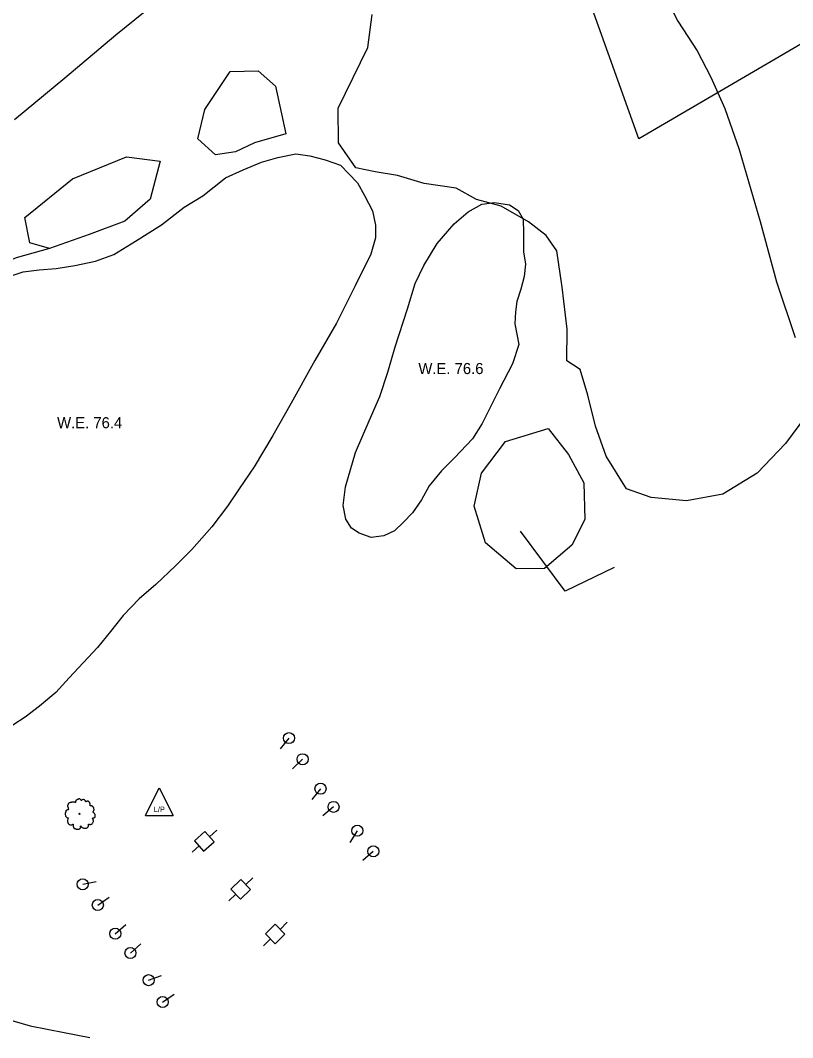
# Model space of a CAD drawing. Extents: x 2161152 to 2175754, y 602179 to 617749.
# Drawn here: x 2172503.3 to 2172781.8, y 613495.8 to 613862.8 of the extents above; entities that cross this region are included whole.
import ezdxf

# ---------------------------------------------------------------- set-up
doc = ezdxf.new("R2010")
doc.units = 0
for name, color, linetype in [('RD_EX_Driveway_Dirt', 7, 'Continuous'), ('RD_EX_Fence_ChLk', 7, 'Continuous'), ('RD_EX_H2O', 7, 'Continuous'), ('RD_EX_H2O_txCode', 7, 'Continuous'), ('RD_EX_UT', 7, 'Continuous'), ('RD_EX_VEG', 7, 'Continuous')]:
    doc.layers.add(name, color=color, linetype=linetype)

msp = doc.modelspace()

# ---------------------------------------------------------------- linework, layer by layer
at = {"layer": 'RD_EX_Driveway_Dirt'}
msp.add_lwpolyline([(2172493.13, 613504.13), (2172506.78, 613500.11), (2172519.03, 613497.66), (2172528.38, 613495.84)], dxfattribs=at)
at = {"layer": 'RD_EX_Fence_ChLk'}
for points in [[(2172849.56, 613892.25), (2172726.3, 613820.12), (2172700.67, 613891.74), (2172702.95, 613909.79), (2172721.51, 613939.42), (2172751.74, 613974.63), (2172793.62, 613997.53), (2172878.3, 614033.31), (2172955.81, 614058.36), (2172981.68, 614063.33), (2173110.09, 614093.24)], [(2172717.4, 613665.4), (2172699.75, 613656.86), (2172683.65, 613678.5)]]:
    msp.add_lwpolyline(points, dxfattribs=at)
at = {"layer": 'RD_EX_H2O'}
for points in [[(2172497.49, 613769.8), (2172504.35, 613772.09), (2172510.1, 613772.82), (2172516.17, 613773.34), (2172522.92, 613774.37), (2172530.42, 613775.98), (2172536.95, 613778.35), (2172544.76, 613783.2), (2172554.14, 613789.12), (2172562.4, 613795.42), (2172569.12, 613799.51), (2172577.26, 613806.08), (2172583.67, 613808.85), (2172590.21, 613811.62), (2172596.19, 613813.34), (2172602.68, 613814.65), (2172607.71, 613813.94), (2172613.17, 613812.49), (2172618.76, 613810.64), (2172621.71, 613807.48), (2172624.86, 613804.25), (2172627.36, 613799.64), (2172630.22, 613794.09), (2172631.31, 613788.93), (2172631.35, 613784.35), (2172629.62, 613778.49), (2172623.98, 613767.05), (2172617.26, 613753.58), (2172609.49, 613740.15), (2172600.98, 613724.75), (2172594.33, 613713.01), (2172587.62, 613701.74), (2172582.16, 613693.81), (2172577.96, 613687.57), (2172572.39, 613680.18), (2172565.12, 613671.98), (2172559.26, 613666), (2172552.12, 613659.33), (2172546.15, 613654.15), (2172540.36, 613648.09), (2172535.77, 613642.4), (2172531.05, 613636.57), (2172520.9, 613625.68), (2172516.13, 613620.33), (2172510.17, 613615.41), (2172504.98, 613611.46), (2172500.62, 613608.55)], [(2172634.32, 613676.84), (2172629.78, 613676.33), (2172625.44, 613677.81), (2172622.71, 613679.63), (2172620.7, 613682.89), (2172619.67, 613687.85), (2172620.5, 613694.54), (2172624.18, 613706.98), (2172629.1, 613718.38), (2172632.86, 613727.16), (2172635.82, 613735.97), (2172638.39, 613745.06), (2172642.92, 613758.8), (2172645.62, 613767.88), (2172648.77, 613774.42), (2172653.63, 613782.29), (2172659.72, 613789.4), (2172664.73, 613793.81), (2172669.74, 613796.56), (2172674.22, 613797.14), (2172679.64, 613796.29), (2172682.76, 613794.19), (2172684.58, 613791.14), (2172684.74, 613786.01), (2172684.7, 613779.3), (2172685.41, 613774.82), (2172685, 613770.45), (2172683.71, 613765.9), (2172682.36, 613761.43), (2172681.84, 613757.72), (2172681.62, 613753.41), (2172683.02, 613745.85), (2172680.79, 613738.88), (2172676.09, 613729.86), (2172669.81, 613717.45), (2172666.3, 613711.85), (2172659.88, 613704.96), (2172655.2, 613700.33), (2172650.69, 613694.96), (2172647.92, 613689.81), (2172644.64, 613685.2), (2172641.33, 613681.72), (2172638.23, 613678.7), (2172634.32, 613676.84)]]:
    msp.add_lwpolyline(points, dxfattribs=at)
at = {"layer": 'RD_EX_UT'}
for p, q in [((2172600.14, 613603.9), (2172596.94, 613600.06)), ((2172605.06, 613596.28), (2172601.41, 613592.87)), ((2172548.39, 613575.93), (2172553.39, 613585.93)), ((2172553.39, 613585.93), (2172558.39, 613575.93)), ((2172611.54, 613585.63), (2172608.37, 613581.76)), ((2172616.23, 613579.09), (2172612.41, 613575.87)), ((2172548.39, 613575.93), (2172558.39, 613575.93)), ((2172569.83, 613570.2), (2172566.08, 613566.89)), ((2172573.14, 613566.46), (2172569.83, 613570.2)), ((2172571.47, 613568.24), (2172574.2, 613570.64)), ((2172624.78, 613570.49), (2172622.09, 613566.27)), ((2172565.2, 613562.7), (2172567.8, 613565)), ((2172566.08, 613566.89), (2172569.39, 613563.15)), ((2172569.39, 613563.15), (2172573.14, 613566.46)), ((2172630.57, 613563.05), (2172626.82, 613559.74)), ((2172582.78, 613552.88), (2172579.17, 613549.42)), ((2172586.24, 613549.27), (2172582.78, 613552.88)), ((2172584.5, 613550.98), (2172587.12, 613553.5)), ((2172525.76, 613551.17), (2172530.65, 613552.21)), ((2172579.17, 613549.42), (2172582.63, 613545.81)), ((2172582.63, 613545.81), (2172586.24, 613549.27)), ((2172531.22, 613543.67), (2172535.28, 613546.58)), ((2172578.46, 613545.2), (2172580.97, 613547.6)), ((2172537.51, 613533.35), (2172541.27, 613536.65)), ((2172595.18, 613536.77), (2172591.64, 613533.24)), ((2172598.71, 613533.22), (2172595.18, 613536.77)), ((2172596.94, 613534.9), (2172599.52, 613537.47)), ((2172591.01, 613529), (2172593.47, 613531.45)), ((2172591.64, 613533.24), (2172595.17, 613529.69)), ((2172595.17, 613529.69), (2172598.71, 613533.22)), ((2172542.99, 613526.38), (2172546.73, 613529.69)), ((2172549.55, 613516.58), (2172554.24, 613518.31)), ((2172554.6, 613508.7), (2172558.7, 613511.56))]:
    msp.add_line(p, q, dxfattribs=at)
for centre in [(2172600.14, 613603.9), (2172605.06, 613596.28), (2172611.54, 613585.63), (2172616.23, 613579.09), (2172624.78, 613570.49), (2172630.57, 613563.05), (2172525.76, 613551.17), (2172531.22, 613543.67), (2172537.51, 613533.35), (2172542.99, 613526.38), (2172549.55, 613516.58), (2172554.6, 613508.7)]:
    msp.add_circle(centre, 2, dxfattribs=at)
at = {"layer": 'RD_EX_VEG'}
for points in [[(2172794.18, 613955.78), (2172775.67, 613946.71), (2172756.66, 613931.17), (2172744.24, 613915.51), (2172736.73, 613900.96), (2172736.22, 613886.41), (2172735.2, 613872.66), (2172740.33, 613862.52), (2172747.3, 613851.81), (2172752.31, 613842.33), (2172757.28, 613830.99), (2172762.47, 613816.2), (2172770.12, 613790.25), (2172775.98, 613768.56), (2172782.67, 613748.44)], [(2172501.12, 613827.07), (2172519.38, 613842.07), (2172537.66, 613857.6), (2172555.1, 613871.83)], [(2172788.88, 613723.16), (2172779.26, 613710.19), (2172769, 613699.49), (2172756.55, 613691.87), (2172743.51, 613689.44), (2172730.8, 613690.71), (2172721.83, 613693.78), (2172714.59, 613705.57), (2172710.66, 613716.39), (2172707.92, 613727.58), (2172705.16, 613736.92), (2172700.3, 613740.05), (2172700.49, 613751.47), (2172698.62, 613766.63), (2172696.71, 613779.67), (2172692.95, 613785.17), (2172686.53, 613790.19), (2172676.66, 613795.8), (2172667.8, 613798.21), (2172660.43, 613802.31), (2172648.9, 613803.96), (2172639.26, 613806.91), (2172631.18, 613808.24), (2172624.29, 613809.68), (2172618, 613818.62), (2172617.88, 613831.17), (2172628.6, 613853.03), (2172630.12, 613864.95)], [(2172598.97, 613821.94), (2172587.69, 613818.6), (2172580.93, 613815.38), (2172573.72, 613814.3), (2172567.28, 613820.1), (2172569.76, 613830.65), (2172579, 613844.41), (2172589.1, 613844.59), (2172595.29, 613839.07), (2172598.97, 613821.94)], [(2172550.05, 613798.37), (2172541, 613790.43), (2172528.07, 613785.56), (2172513.81, 613780.47), (2172506.7, 613782.57), (2172504.89, 613791.67), (2172522.11, 613805.7), (2172541.52, 613813.54), (2172553.69, 613812.06), (2172550.05, 613798.37)], [(2172513.81, 613780.47), (2172501.73, 613777.16), (2172491.48, 613772.99), (2172480.02, 613764.61), (2172467.5, 613752.14), (2172454.53, 613741.76)], [(2172693.67, 613715.57), (2172700.92, 613706.16), (2172706.54, 613696.01), (2172706.88, 613682.72), (2172702.19, 613673.45), (2172692.34, 613665.03), (2172682.11, 613664.98), (2172671.02, 613674.39), (2172666.95, 613687.55), (2172669.62, 613699.54), (2172678.25, 613710.94), (2172693.67, 613715.57)]]:
    msp.add_lwpolyline(points, dxfattribs=at)
for centre, radius in [((2172524.64, 613576.59), 0.188), ((2172524.63, 613576.57), 0.000075)]:
    msp.add_circle(centre, radius, dxfattribs=at)
for points in [[(2172524.74, 613581.96), (2172524.52, 613581.98), (2172524.27, 613581.91), (2172524.09, 613581.83), (2172523.92, 613581.77), (2172523.75, 613581.7), (2172523.52, 613581.57), (2172523.35, 613581.42), (2172523.26, 613581.23), (2172523.22, 613581.06), (2172523.19, 613580.86), (2172523.19, 613580.72), (2172523.09, 613580.71), (2172522.98, 613580.72), (2172522.79, 613580.78), (2172522.6, 613580.78), (2172522.42, 613580.78), (2172522.16, 613580.76), (2172521.89, 613580.76), (2172521.69, 613580.72), (2172521.44, 613580.69), (2172521.16, 613580.59), (2172520.9, 613580.5), (2172520.67, 613580.31), (2172520.49, 613579.96), (2172520.39, 613579.69), (2172520.28, 613579.51), (2172520.39, 613579.17), (2172520.52, 613578.91), (2172520.54, 613578.76), (2172520.6, 613578.44), (2172520.67, 613578.27), (2172520.77, 613578.12), (2172520.71, 613578.1), (2172520.43, 613578.06), (2172520.21, 613577.99), (2172519.89, 613577.82), (2172519.72, 613577.65), (2172519.64, 613577.41), (2172519.62, 613577.14), (2172519.55, 613576.99), (2172519.49, 613576.79), (2172519.47, 613576.73), (2172519.44, 613576.49), (2172519.51, 613576.15), (2172519.53, 613575.89), (2172519.62, 613575.72), (2172519.74, 613575.59), (2172519.87, 613575.4), (2172520.17, 613575.23), (2172520.41, 613575.16), (2172520.56, 613575.14), (2172520.43, 613574.76), (2172520.39, 613574.5), (2172520.3, 613574.2), (2172520.3, 613574.15), (2172520.26, 613573.79), (2172520.37, 613573.55), (2172520.43, 613573.27), (2172520.56, 613573.1), (2172520.77, 613572.87), (2172521.01, 613572.7), (2172521.39, 613572.61), (2172521.69, 613572.63), (2172522.12, 613572.76), (2172522.3, 613572.82), (2172522.29, 613572.68), (2172522.3, 613572.4), (2172522.3, 613572.08), (2172522.42, 613571.84), (2172522.49, 613571.63), (2172522.6, 613571.45), (2172522.85, 613571.28), (2172523.15, 613571.22), (2172523.47, 613571.11), (2172523.8, 613571.05), (2172524.18, 613571.04), (2172524.63, 613571.15), (2172524.84, 613571.24), (2172524.91, 613571.37), (2172525.06, 613571.65), (2172525.02, 613571.82), (2172525.04, 613572.27), (2172525.12, 613572.14), (2172525.25, 613571.88), (2172525.62, 613571.65), (2172525.92, 613571.52), (2172526.28, 613571.41), (2172526.5, 613571.35), (2172526.86, 613571.41), (2172527.14, 613571.47), (2172527.42, 613571.56), (2172527.65, 613571.77), (2172527.78, 613571.97), (2172527.82, 613572.18), (2172527.87, 613572.46), (2172527.91, 613572.59)], [(2172527.91, 613572.59), (2172527.85, 613572.72), (2172527.82, 613572.91), (2172527.87, 613572.89), (2172528, 613572.85), (2172528.21, 613572.76), (2172528.38, 613572.7), (2172528.62, 613572.72), (2172528.83, 613572.8), (2172529.16, 613573), (2172529.37, 613573.36), (2172529.58, 613573.66), (2172529.63, 613573.9), (2172529.6, 613574.07), (2172529.58, 613574.45), (2172529.43, 613574.63), (2172529.39, 613574.73), (2172529.31, 613575.03), (2172529.37, 613575.06), (2172529.58, 613575.1), (2172529.86, 613575.2), (2172530.06, 613575.29), (2172530.23, 613575.42), (2172530.29, 613575.59), (2172530.27, 613575.89), (2172530.31, 613576.19), (2172530.25, 613576.3), (2172530.18, 613576.41), (2172530.12, 613576.56), (2172530.01, 613576.68), (2172529.93, 613576.79), (2172529.86, 613576.86), (2172529.76, 613576.98), (2172529.63, 613577.07), (2172529.52, 613577.11), (2172529.48, 613577.22), (2172529.6, 613577.37), (2172529.63, 613577.44), (2172529.65, 613577.61), (2172529.82, 613577.88), (2172529.86, 613578.18), (2172529.82, 613578.49), (2172529.78, 613578.7), (2172529.67, 613578.91), (2172529.52, 613579.09), (2172529.43, 613579.23), (2172529.3, 613579.32), (2172529.05, 613579.41), (2172528.86, 613579.45), (2172528.6, 613579.45), (2172528.45, 613579.49), (2172528.47, 613579.53), (2172528.47, 613579.64), (2172528.47, 613579.84), (2172528.41, 613580.18), (2172528.3, 613580.56), (2172528.3, 613580.57), (2172528.23, 613580.76), (2172528.06, 613580.91), (2172527.93, 613580.99), (2172527.78, 613581.08), (2172527.59, 613581.1), (2172527.37, 613581.1), (2172527.16, 613581.06), (2172527.01, 613580.99), (2172526.88, 613580.89), (2172526.82, 613581.01), (2172526.75, 613581.23), (2172526.71, 613581.34), (2172526.6, 613581.47), (2172526.43, 613581.62), (2172526.09, 613581.72), (2172525.62, 613581.66), (2172525.4, 613581.51), (2172525.28, 613581.38), (2172525.25, 613581.47), (2172525.1, 613581.62), (2172525.02, 613581.76), (2172524.89, 613581.85), (2172524.78, 613581.92), (2172524.7, 613581.96)]]:
    msp.add_spline(points, degree=3, dxfattribs=at)

# ---------------------------------------------------------------- texts
at = {"layer": 'RD_EX_H2O_txCode'}
for s, p in [('W.E. 76.6', (2172646.82, 613735.23)), ('W.E. 76.4', (2172516.54, 613715.69))]:
    msp.add_text(s, height=4, dxfattribs=at).set_placement(p)
at = {"layer": 'RD_EX_UT'}
msp.add_text('L/P', height=2, dxfattribs=at).set_placement((2172551.38, 613577.21))

doc.saveas('drawing.dxf')
